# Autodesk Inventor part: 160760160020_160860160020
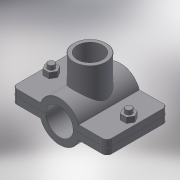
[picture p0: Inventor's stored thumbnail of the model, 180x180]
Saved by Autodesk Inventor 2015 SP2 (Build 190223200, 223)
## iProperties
Created: 2017-05
Part Number: 160760160020_160860160020
Material: Generic
Description: PLASSON SADDLE 160-2"
Document SubType Name: Modeling
Designer: KIM
Density: 1 g/cm^3
Appearance: Default
Author: KIM
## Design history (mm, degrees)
derived "16076.ipt"
feature "Solid1::16076.ipt"
feature "Solid2::16076.ipt"
tag "TaggingFeature1"
body "Solid1"
other parameters: "d0" = 176, "d1" = 223, "d4" = 145, "d5" = 0, "d6" = 11.15, "d7" = 223, "d8" = 0.1, "d10" = 0, "d11" = 1.6, "d14" = 73.6528, "d20" = 1.6, "d23" = 1.6, "d36" = 15, "d37" = 12, "d38" = 88, "d39" = 0, "d40" = 3, "d41" = 5, "d42" = 0, "d44" = 3, "d45" = 0, "d46" = 1.6, "d51" = 123, "d52" = 56.656, "d54" = 0, "d57" = 0, "d58" = 172.8, "d60" = 0, "d62" = 15, "d63" = 12, "d66" = 121, "G_" = 56.656, "A_" = 123, "L_" = 223, "L_1" = 145
